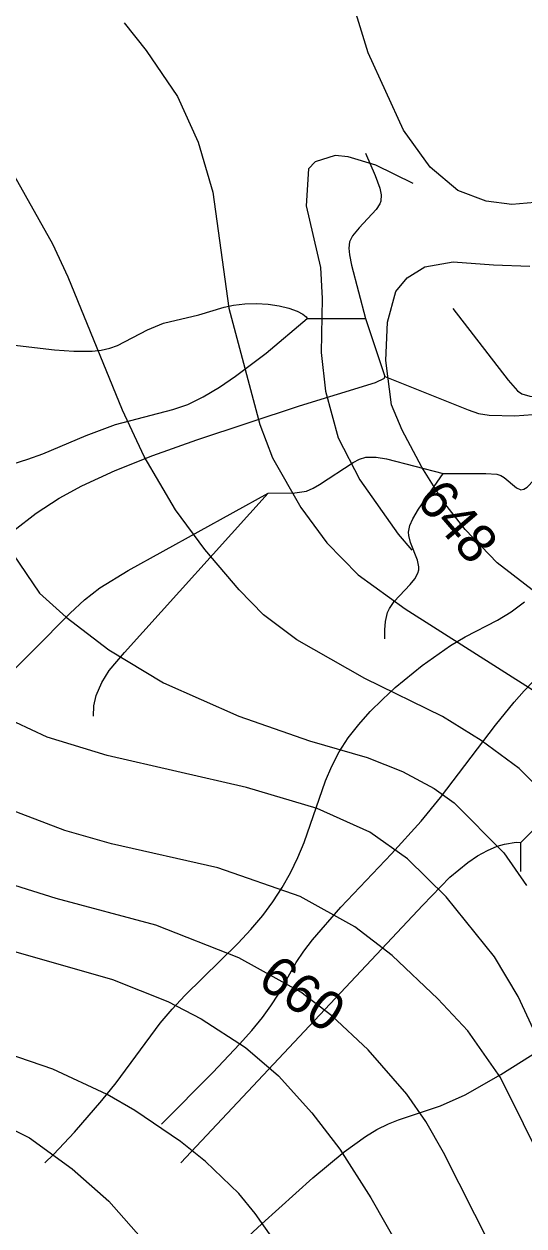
# Model space of a CAD drawing. Extents: x -709584 to -702006, y -1161789 to -1157496.
# Drawn here: x -705974.9 to -705846.2, y -1161250.8 to -1160941.2 of the extents above; entities that cross this region are included whole.
import ezdxf

# ---------------------------------------------------------------- set-up
doc = ezdxf.new("R2010")
doc.units = 0
for name, color, linetype in [('120_vrstevnice hlavní', 7, 'Continuous'), ('121_vrstevnice hlavní_popis', 7, 'Continuous'), ('122_vrstevnice základní', 7, 'Continuous'), ('124_vrstevnice doplňková', 7, 'Continuous'), ('411_akumulovaný odtok', 7, 'Continuous')]:
    doc.layers.add(name, color=color, linetype=linetype)

msp = doc.modelspace()

# ---------------------------------------------------------------- linework, layer by layer
at = {"layer": '120_vrstevnice hlavní'}
for points in [[(-705843.36, -1160987.14), (-705849.29, -1160987.71), (-705855.9, -1160986.8), (-705863.19, -1160984.09), (-705870.35, -1160978.07), (-705877.14, -1160968.53), (-705886.26, -1160948.58), (-705891.87, -1160930.38), (-705892.82, -1160915.24), (-705891.96, -1160910.4), (-705890.45, -1160905.39), (-705887.54, -1160900.71)], [(-705949.1, -1160940.89), (-705943.4, -1160948.02), (-705935.39, -1160959.89), (-705930.01, -1160971.67), (-705926.3, -1160984.49), (-705922.17, -1161014.42), (-705914.19, -1161044.34), (-705910.91, -1161052.89), (-705903.65, -1161065.72), (-705896.95, -1161074.83), (-705888.83, -1161083.1)], [(-705940.98, -1161173.3), (-705966.63, -1161166.46), (-706013.65, -1161151.64), (-706032.18, -1161143.66), (-706046.71, -1161135.39), (-706056.26, -1161129.27), (-706065.23, -1161122.43), (-706077.92, -1161111.46), (-706093.87, -1161096.07), (-706111.12, -1161081.25), (-706119.38, -1161075.12), (-706124.51, -1161072.13), (-706138.33, -1161065.57), (-706157, -1161059.45), (-706174.1, -1161055.46)], [(-705888.83, -1161083.1), (-705876.71, -1161091.79), (-705843.8, -1161112.74)], [(-705830.26, -1161299.69), (-705850.78, -1161263.78), (-705866.88, -1161231.86), (-705871.44, -1161223.88), (-705876.35, -1161216.78), (-705886.26, -1161205.36), (-705895.67, -1161196.67), (-705903.65, -1161190.54), (-705919.6, -1161181.71), (-705940.98, -1161173.3)]]:
    msp.add_lwpolyline(points, dxfattribs=at)
at = {"layer": '122_vrstevnice základní'}
for points in [[(-705839.81, -1161140.38), (-705847.36, -1161132.97), (-705857.19, -1161125.71), (-705867.17, -1161119.58), (-705887.12, -1161109.75), (-705904.64, -1161099.77), (-705913.19, -1161093.36), (-705919.46, -1161086.95), (-705928.3, -1161076.54), (-705935.85, -1161066.28), (-705943.97, -1161052.61), (-705949.53, -1161040.64), (-705963.49, -1161006.44), (-705967.48, -1160997.89), (-705978.03, -1160979.08), (-705988.86, -1160965.4), (-705999.26, -1160954.86)], [(-705836.96, -1161214.76), (-705847.64, -1161191.68), (-705853.77, -1161181.42), (-705866.17, -1161166.03), (-705876.14, -1161156.2), (-705885.83, -1161149.36), (-705899.37, -1161143.23), (-705917.61, -1161137.82), (-705953.52, -1161129.55), (-705968.91, -1161124.85), (-705985.15, -1161117.3), (-705992.28, -1161112.45), (-705999.69, -1161105.47), (-706009.09, -1161093.93), (-706017.35, -1161081.11), (-706046.42, -1161042.63), (-706061.53, -1161028.24), (-706074.35, -1161019.83), (-706093.02, -1161010.71), (-706112.54, -1161003.02), (-706127.93, -1160998.03), (-706148.73, -1160989.62), (-706180.08, -1160979.08)], [(-705830.55, -1161097.35), (-705853.06, -1161079.97), (-705861.32, -1161071.42), (-705866.88, -1161064.29), (-705872.46, -1161055.34), (-705877.53, -1161045.83), (-705880.25, -1161039.27), (-705881.71, -1161027.9), (-705881.33, -1161017.99), (-705879.12, -1161010.05), (-705876.27, -1161006.59), (-705871.68, -1161003.73), (-705864.43, -1161002.49), (-705854.03, -1161003.18), (-705844.62, -1161003.56)], [(-705852.2, -1161212.48), (-705860.61, -1161200.52), (-705868.31, -1161192.25), (-705880.13, -1161181.14), (-705889.68, -1161173.73), (-705903.79, -1161165.89), (-705925.02, -1161158.48), (-705952.38, -1161152.35), (-705964.35, -1161148.93), (-705991.71, -1161138.53), (-706009.23, -1161129.84), (-706022.48, -1161121.57), (-706027.05, -1161118.01), (-706035.59, -1161109.75), (-706047.42, -1161094.36), (-706056.26, -1161081.67), (-706068.65, -1161066.28), (-706075.35, -1161058.88), (-706087.04, -1161047.9), (-706104.42, -1161036.36), (-706115.11, -1161030.8), (-706132.06, -1161023.39), (-706146.6, -1161017.84), (-706172.53, -1161009.29)], [(-705987.29, -1161061.73), (-705981.3, -1161072.55), (-705970.9, -1161087.8), (-705964.06, -1161093.93), (-705953.09, -1161102.34), (-705938.98, -1161110.89), (-705919.6, -1161119.44), (-705901.37, -1161125.85), (-705886.55, -1161130.12), (-705877.43, -1161133.68), (-705869.3, -1161138.1), (-705864.17, -1161141.81), (-705851.35, -1161154.63), (-705845.51, -1161163.04)], [(-706171.53, -1161085.52), (-706151.58, -1161093.64), (-706145.89, -1161097.06), (-706117.39, -1161119.15), (-706103.14, -1161129.27), (-706091.74, -1161138.53), (-706080.34, -1161146.65), (-706060.39, -1161157.91), (-706043.29, -1161165.18), (-706026.19, -1161170.31), (-706009.09, -1161174.01), (-705980.59, -1161179.14), (-705952.09, -1161187.26), (-705937.84, -1161192.96), (-705929.29, -1161197.38), (-705917.89, -1161204.79), (-705909.34, -1161212.06), (-705900.8, -1161221.6), (-705893.53, -1161231.01), (-705885.55, -1161243.55), (-705864.17, -1161281.17)], [(-706466.21, -1161149.07), (-706440.56, -1161152.92), (-706433.72, -1161153.06), (-706401.81, -1161151.07), (-706357.92, -1161146.37), (-706314.03, -1161141.38), (-706284.39, -1161139.53), (-706266.44, -1161139.53), (-706252.19, -1161140.52), (-706224.83, -1161144.09), (-706210.3, -1161147.79), (-706194.05, -1161153.21), (-706183.79, -1161158.05), (-706146.17, -1161178.43), (-706120.52, -1161188.26), (-706110.26, -1161191.4), (-706004.25, -1161216.05), (-705985.44, -1161222.17), (-705973.47, -1161228.02), (-705962.5, -1161236), (-705953.09, -1161244.4), (-705932.57, -1161267.63)], [(-705905.78, -1161261.22), (-705915.33, -1161247.54), (-705919.6, -1161242.41), (-705928.15, -1161234.14), (-705934.57, -1161229.01), (-705946.39, -1161221.03), (-705953.52, -1161216.9), (-705967.48, -1161210.35), (-705988.29, -1161203.22), (-706003.96, -1161199.38), (-706021.06, -1161196.67), (-706092.88, -1161182.13), (-706111.83, -1161176.15), (-706124.51, -1161170.59), (-706151.58, -1161154.06), (-706171.82, -1161139.95)], [(-705840.38, -1161236.42), (-705852.2, -1161212.48)]]:
    msp.add_lwpolyline(points, dxfattribs=at)
at = {"layer": '124_vrstevnice doplňková'}
msp.add_lwpolyline([(-705874.65, -1160982.27), (-705884.27, -1160977.51), (-705891.39, -1160975.37), (-705894.81, -1160975.09), (-705899.94, -1160976.66), (-705901.65, -1160978.51), (-705902.22, -1160988.05), (-705898.52, -1161003.87), (-705898.09, -1161011.85), (-705898.37, -1161025.82), (-705897.23, -1161035.79), (-705893.96, -1161047.76), (-705888.4, -1161058.59), (-705878.57, -1161072.55), (-705875, -1161076.69)], dxfattribs=at)
at = {"layer": '411_akumulovaný odtok'}
for p, q in [((-705901.99, -1161017), (-705886.99, -1161017)), ((-705886.99, -1161017), (-705881.99, -1161032)), ((-705846.99, -1161159.5), (-705846.99, -1161152))]:
    msp.add_line(p, q, dxfattribs=at)
for points in [[(-705886.99, -1160974.5), (-705884.5, -1160980.23), (-705883.31, -1160983.45), (-705882.95, -1160985.16), (-705883.02, -1160986.79), (-705883.3, -1160987.53), (-705884.21, -1160988.95), (-705888.63, -1160993.67), (-705890.33, -1160995.76), (-705891.06, -1160997.26), (-705891.26, -1160998.89), (-705891.11, -1161000.63), (-705890.57, -1161003.32), (-705886.99, -1161017)], [(-705979.46, -1161023.68), (-705967.01, -1161025.07), (-705962.1, -1161025.45), (-705957.31, -1161025.45), (-705955, -1161025.2), (-705952.77, -1161024.71), (-705950.78, -1161023.99), (-705943.12, -1161019.97), (-705938.97, -1161018.28), (-705929.86, -1161016.13), (-705923.38, -1161014.16), (-705920.92, -1161013.59), (-705918.04, -1161013.25), (-705915.03, -1161013.19), (-705912.03, -1161013.39), (-705909.19, -1161013.8), (-705906.66, -1161014.42), (-705904.57, -1161015.18), (-705903.12, -1161015.95), (-705902.24, -1161016.61), (-705901.99, -1161017)], [(-705864.49, -1161014.5), (-705850.24, -1161032.93), (-705847.82, -1161035.65), (-705846.71, -1161036.44), (-705844.69, -1161037.02), (-705841.95, -1161037.14), (-705836.99, -1161037)], [(-705977.72, -1161054.43), (-705973.87, -1161053.27), (-705970.08, -1161051.88), (-705958.88, -1161047.17), (-705951.34, -1161044.34), (-705936.54, -1161040.5), (-705932.74, -1161039.16), (-705928.74, -1161037.21), (-705924.58, -1161034.73), (-705920.41, -1161031.92), (-705912.54, -1161025.96), (-705901.99, -1161017)], [(-705977.53, -1161071.6), (-705971.75, -1161067.18), (-705965.84, -1161063.28), (-705960.02, -1161060.18), (-705951.38, -1161056.19), (-705941.73, -1161052.29), (-705930.36, -1161048.29), (-705903.94, -1161039.52), (-705884.39, -1161033.5), (-705882.07, -1161032.42), (-705881.99, -1161032)], [(-705881.99, -1161032), (-705860.56, -1161040.6), (-705857.83, -1161041.47), (-705855.08, -1161041.94), (-705848.55, -1161042.12), (-705843.91, -1161041.79), (-705841.85, -1161041.06), (-705840.9, -1161040.5), (-705839.18, -1161039.19), (-705836.99, -1161037)], [(-705911.99, -1161062), (-705905.18, -1161061.98), (-705902.14, -1161061.47), (-705900.46, -1161060.75), (-705898.84, -1161059.82), (-705890.14, -1161054.11), (-705888.52, -1161053.28), (-705886.86, -1161052.75), (-705884.25, -1161052.74), (-705881.56, -1161053.22), (-705866.99, -1161057)], [(-705881.99, -1161099.5), (-705882.01, -1161097.24), (-705881.8, -1161095.06), (-705881.26, -1161092.8), (-705880.77, -1161091.69), (-705879.56, -1161089.94), (-705875.48, -1161085.58), (-705874.3, -1161084.12), (-705873.45, -1161082.6), (-705873.24, -1161081.81), (-705873.23, -1161080.98), (-705873.6, -1161079.25), (-705875.35, -1161074.77), (-705875.82, -1161072.97), (-705875.88, -1161072.09), (-705875.54, -1161070.37), (-705874.78, -1161068.68), (-705873.29, -1161066.16), (-705866.99, -1161057)], [(-705866.99, -1161057), (-705855.99, -1161056.95), (-705853.18, -1161057.16), (-705852.15, -1161057.46), (-705851.26, -1161057.97), (-705848.11, -1161060.67), (-705846.96, -1161061.19), (-705846.2, -1161061.02), (-705845.35, -1161060.44), (-705841.99, -1161057)], [(-705981.99, -1161112), (-705962.99, -1161092.9), (-705959.3, -1161089.48), (-705955.33, -1161086.38), (-705948.03, -1161081.95), (-705911.99, -1161062)], [(-705956.99, -1161119.5), (-705956.89, -1161116.76), (-705956.32, -1161114.12), (-705954.89, -1161110.75), (-705952.96, -1161107.7), (-705949.02, -1161103.1), (-705911.99, -1161062)], [(-705939.49, -1161224.5), (-705926.23, -1161211.26), (-705919.37, -1161203.96), (-705916.23, -1161200.4), (-705913.5, -1161197.07), (-705911.3, -1161194.06), (-705909.36, -1161191.04), (-705904.82, -1161182.92), (-705902.84, -1161179.94), (-705900.64, -1161177.04), (-705893.32, -1161168.65), (-705880.25, -1161154.95), (-705872.6, -1161146.49), (-705867.68, -1161140.43), (-705853.52, -1161121.8), (-705848.66, -1161115.82), (-705846.13, -1161112.96), (-705836.57, -1161103.04), (-705834.13, -1161100.14), (-705826.96, -1161090.8), (-705824.09, -1161087.6), (-705818.39, -1161082.11), (-705813.9, -1161078.36), (-705811.99, -1161077)], [(-705846.99, -1161152), (-705823.54, -1161128.74), (-705820.37, -1161125.31), (-705817.63, -1161121.62), (-705815.78, -1161117.6), (-705814.36, -1161113.33), (-705806.99, -1161087)], [(-705969.49, -1161234.5), (-705967.28, -1161232.36), (-705961.88, -1161226.6), (-705954.81, -1161218.47), (-705951.15, -1161213.88), (-705939.8, -1161198.53), (-705936.71, -1161194.9), (-705933.44, -1161191.43), (-705919.77, -1161177.93), (-705916.5, -1161174.43), (-705913.43, -1161170.79), (-705910.82, -1161167.27), (-705908.43, -1161163.61), (-705906.26, -1161159.82), (-705904.35, -1161155.89), (-705902.76, -1161152), (-705897.24, -1161136.14), (-705895.65, -1161132.32), (-705893.78, -1161128.67), (-705891.42, -1161125.02), (-705888.72, -1161121.58), (-705885.76, -1161118.29), (-705882.6, -1161115.14), (-705879.3, -1161112.11), (-705872.35, -1161106.4), (-705865.05, -1161101.27), (-705861.28, -1161099.01), (-705852.99, -1161094.71), (-705849.42, -1161092.62), (-705846.03, -1161090.05)], [(-705934.49, -1161234.5), (-705872.17, -1161168.1), (-705865.23, -1161160.94), (-705860.63, -1161157.17), (-705858.09, -1161155.46), (-705855.53, -1161154.03), (-705853.04, -1161152.96), (-705851.17, -1161152.4), (-705848.21, -1161151.93), (-705846.99, -1161152)], [(-705946.99, -1161287), (-705941.7, -1161279.92), (-705936.28, -1161273.12), (-705930.1, -1161266.05), (-705924.11, -1161259.9), (-705913.69, -1161250.18), (-705900.53, -1161238.38), (-705892.47, -1161231.69), (-705886.92, -1161227.7), (-705884.04, -1161225.95), (-705881.07, -1161224.44), (-705878.45, -1161223.39), (-705867.66, -1161219.85), (-705861.33, -1161217.02), (-705852.1, -1161211.78), (-705830.85, -1161198.34), (-705827.31, -1161196.4), (-705823.3, -1161194.47), (-705818.99, -1161192.69), (-705814.49, -1161191.14), (-705810.07, -1161189.85), (-705802.37, -1161188.01), (-705796.99, -1161187)]]:
    msp.add_lwpolyline(points, dxfattribs=at)

# ---------------------------------------------------------------- texts
at = {"layer": '121_vrstevnice hlavní_popis'}
for s, rotation, p in [('648', 310.5915, (-705874.25, -1161064.01)), ('660', 324.8497, (-705915.19, -1161188.5))]:
    msp.add_text(s, height=10, rotation=rotation, dxfattribs=at).set_placement(p)

doc.saveas('drawing.dxf')
